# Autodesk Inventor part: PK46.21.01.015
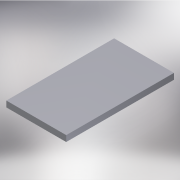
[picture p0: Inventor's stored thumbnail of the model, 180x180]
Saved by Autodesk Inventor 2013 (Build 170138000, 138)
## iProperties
Created: 2005-04
Part Number: PK46.21.01.015
Material: Steel, Mild
Document SubType Name: Modeling
Designer: salex
Manufacturer: Standard
Standards Organization: Custom
Density: 7.86 g/cm^3
Author: salex
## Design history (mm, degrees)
sketch "Эскиз1"
  geometry: L1 (0, 0)-(100, 0); L2 (100, 0)-(100, 180); L3 (100, 180)-(0, 180); L4 (0, 180)-(0, 0)
  constraints: 8 end point, 2 parallel, 1 horizontal, 1 perpendicular, 1 other
  dimensions: "d0" = 180 distance of L3.end L1.start; "d1" = 100 distance of L1.start L1.end
extrude "Выдавливание1" new body sketch "Эскиз1" distance "d2" = 10; taper "d3" = 0 deg
body "Solid1"
